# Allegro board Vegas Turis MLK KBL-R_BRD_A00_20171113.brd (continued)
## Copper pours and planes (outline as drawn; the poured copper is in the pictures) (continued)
+DC_IN on TOP: 80.87,167.46 80.07,168.25 78.24,168.25 77.99,168.51 77.22,168.51 76.67,169.06 68.06,169.06 66.11,171.01 66.11,174.44 66,174.55 65.23,174.55 64.6,175.19 64.6,176.63 64.62,176.66 64.62,178.08 67.52,180.98 70.14,180.98 70.72,180.39 70.72,178.21 71.01,177.92 71.6,177.92 71.83,177.69 71.83,176.59 72.06,176.37 75.91,176.37 76.44,175.84 76.44,173.17 76.69,172.93 80.72,172.93 81.25,172.4 83.19,172.4 83.65,171.93 84.73,171.93 85.51,171.15 85.51,168.31 85.45,168.25 84.74,168.25 83.95,167.46 ; 14 cut-outs
+DC_IN on BOTTOM: 74.88,165.81 74.46,166.22 74.46,172.07 69.91,176.63 68.23,176.63 68.14,176.72 68.14,177.26 68.14,177.26 68.14,180.55 68.33,180.74 70.35,180.74 70.67,180.42 70.67,179.5 76.94,173.22 78.47,173.22 78.77,172.92 78.77,170.55 76.86,168.64 76.86,166.11 76.56,165.81
+SDC_IN on TOP: 119.28,160.38 119.03,160.62 119.03,163.78 119.11,163.86 120.28,163.86 120.35,163.93 120.35,165.28 120.61,165.53 120.61,165.58 120.66,165.64 122.31,165.64 122.33,165.61 122.33,160.61 122.1,160.38
+UZ12_TPM on BOTTOM: 160.3,52.71 160.19,52.83 160.19,54.08 159.4,54.87 159.4,54.89 157.8,56.48 157.8,57.06 157.89,57.15 160.23,57.15 160.82,56.56 160.82,52.78 160.75,52.71 ; 4 cut-outs
+V_VREF_PATH2 on TOP: 96.13,17.05 96.08,17.1 96.08,17.61 96.19,17.73 96.79,17.73 96.8,17.73 97.33,17.73 97.92,18.33 98.33,18.33 98.41,18.24 98.41,17.8 97.66,17.05 ; 1 cut-out
+VCHGR on TOP: 140.77,160.53 140.55,160.76 140.55,167.63 140.98,168.06 144.51,168.06 144.96,167.62 144.96,161 144.48,160.53
+VCHGR on BOTTOM: 140.85,162.08 140.67,162.26 140.67,169.17 141.26,169.75 145.35,169.75 145.5,169.6 145.5,162.36 145.22,162.08
AD+ on TOP: 99.09,161.41 96.79,163.7 92.51,163.7 89.64,166.58 86.31,166.58 85.81,167.08 85.81,171.48 85.22,172.06 85.22,172.49 85.34,172.61 97.5,172.61 99.33,170.78 99.33,168.56 100.56,167.34 101.11,167.34 101.3,167.14 102.4,167.14 102.41,167.15 102.54,167.15 102.73,167.34 112.4,167.34 113.57,168.51 115.04,168.51 115.5,168.05 117.82,168.05 118.04,168.27 119.07,168.27 119.11,168.23 119.11,167.67 118.86,167.41 118.45,167.41 118.3,167.26 118.3,166.06 118.72,165.64 118.72,161.66 118.46,161.41 ; 5 cut-outs
AMBER_LED_BAT on BOTTOM: 186.95,11.75 186.73,11.97 186.73,12.73 187.25,13.25 188.5,13.25 188.5,13.25 189.96,13.25 190.15,13.06 190.15,12.47 189.92,12.24 189.87,12.24 189.37,11.75 ; 2 cut-outs
AUD_AGND on TOP: 164.57,12.39 164.33,12.63 164.33,15.74 164.34,15.75 164.34,17.21 164.44,17.31 165.5,17.31 166.3,16.5 166.3,14.77 166.18,14.65 166.18,12.74 165.83,12.39 ; 7 cut-outs
AUD_AGND on TOP: 173.31,11.59 173.25,11.65 173.25,12.57 174.18,13.5 174.18,13.7 174.38,13.89 177.61,13.89 178.02,14.3 181.39,14.3 181.64,14.05 181.64,13.36 181.44,13.16 178.12,13.16 176.54,11.59 ; 8 cut-outs
AUD_AGND on BOTTOM: 185.35,22.01 187.49,22.01 188.29,21.2 190.37,21.2 190.4,21.18 190.4,20.93 190.37,20.9 188.19,20.9 188.09,20.8 187.1,20.8 186.97,20.94 185.32,20.94 185.25,21.02 185.25,21.9
AUD_AGND on BOTTOM: 168.12,10.65 165.51,13.26 165.51,14.58 164.88,15.22 164.88,15.65 165.07,15.84 165.44,15.84 165.85,15.43 167.86,15.43 168.04,15.24 168.04,14.09 169.8,12.33 172.56,12.33 172.63,12.4 176.09,12.4 176.54,11.95 176.54,11.25 176.38,11.1 176.02,11.1 176,11.11 172.33,11.11 171.87,10.65 ; 1 cut-out
AUD_AGND on BOTTOM: 178.71,13.49 178.63,13.58 178.63,14.57 178.5,14.69 178.5,15.35 178.65,15.5 179.03,15.5 179.03,15.5 179.53,15.5 179.84,15.81 179.84,16.68 179.99,16.83 180.74,16.83 180.99,16.59 180.99,15.61 181.56,15.04 181.56,13.92 181.13,13.49 ; 3 cut-outs
AUD_AGND on L2: 176.56,11.59 170.45,11.59 170.28,11.76 170.28,12.42 170.28,12.43 170.28,14.3 170.79,14.81 171.54,14.81 172.01,15.28 172.01,15.62 171.83,15.8 168.83,15.8 167.77,14.75 166.42,14.75 166.23,14.55 166.23,12.79 165.86,12.42 164.72,12.42 164.47,12.67 164.47,15.87 165.31,16.7 167.27,16.7 167.33,16.64 174.33,16.64 174.44,16.75 174.44,21.14 175.72,22.43 184,22.43 184.17,22.27 187.3,22.27 188.55,21.03 190.15,21.03 190.39,20.79 190.39,20.78 190.42,20.75 190.42,16.26 190.1,15.94 188.1,15.94 187.72,15.56 185.96,15.56 185.79,15.72 184.73,15.72 184.42,15.41 184.42,14.35 183.22,13.15 178.11,13.15
AUD_AGND on L5GND: 168.15,10.62 166.47,12.3 165.14,12.3 164.86,12.58 164.86,15.68 165.08,15.9 165.37,15.9 165.55,16.07 165.55,16.86 166.02,17.33 166.93,17.33 167.3,17.7 168.84,17.7 169.04,17.89 170.19,17.89 170.28,17.81 170.28,16.92 169.73,16.37 168.95,16.37 168.2,15.62 168.2,13.72 169.77,12.15 171.91,12.15 172.25,12.49 172.25,14.82 172.01,15.07 172.01,16.6 172.06,16.65 174.18,16.65 174.43,16.9 174.43,20.64 175.96,22.17 187.36,22.17 188.32,21.22 190.37,21.22 190.4,21.19 190.4,15.88 190.39,15.88 188.1,15.88 187.57,15.35 186.13,15.35 185.83,15.65 184.69,15.65 184.43,15.38 184.43,14.37 183.2,13.14 180.02,13.14 179.79,13.38 178.87,13.38 178.25,12.75 178.25,12.29 177.95,11.99 177.32,11.99 176.42,11.08 172.33,11.08 171.87,10.62
AUD_SPK_L+ on TOP: 155,15.32 155,15.98 155.26,16.24 155.26,18.27 155.76,18.77 156.27,18.77 156.52,18.52 156.52,18.09 156.06,17.63 156.06,15.34 156.04,15.32
AUD_SPK_L+_C on TOP: 154.74,11.69 154.44,11.99 154.44,13.74 155,14.3 155,14.68 155.13,14.81 155.96,14.81 156.06,14.71 156.06,11.79 155.96,11.69
AUD_SPK_L+_C on BOTTOM: 154.41,11.36 154.39,11.38 154.39,13.79 154.54,13.95 155.02,13.95 155.18,13.79 155.18,13.29 155.02,13.13 155.02,11.43 154.95,11.36
AUD_SPK_L- on TOP: 153.3,15.27 153.19,15.37 153.19,16.05 153.27,16.13 153.3,16.13 153.65,16.49 153.65,17.73 153.66,17.74 153.66,18.56 154.57,19.46 154.95,19.46 155.35,19.05 155.35,18.85 154.38,17.88 154.38,16.43 154.24,16.28 154.24,15.34 154.19,15.34 154.11,15.27
AUD_SPK_L-_C on TOP: 153.35,11.71 153.22,11.84 153.22,14.68 153.3,14.76 154.26,14.76 154.39,14.63 154.39,13.97 154.21,13.79 154.21,11.89 154.03,11.71
AUD_SPK_L-_C on BOTTOM: 153.45,11.38 153.19,11.64 153.19,13.69 153.35,13.85 153.8,13.85 154.03,13.62 154.03,11.43 153.98,11.38
AUD_SPK_R+ on TOP: 158.88,15.22 158.78,15.32 158.78,16.95 159.16,17.33 160.1,17.33 160.35,17.57 160.66,17.57 161.11,17.11 161.11,16.87 160.56,16.32 159.83,16.32 159.8,16.28 159.8,15.29 159.72,15.22 ; 1 cut-out
AUD_SPK_R+_C on TOP: 158.96,11.66 158.68,11.94 158.68,13.69 158.69,13.71 158.69,14.65 158.83,14.78 159.7,14.78 159.75,14.73 159.75,11.79 159.62,11.66
AUD_SPK_R+_C on BOTTOM: 156.5,11.33 156.37,11.46 156.37,12.98 156.45,13.06 157.44,13.06 158.17,13.79 159.39,13.79 159.57,13.62 159.57,12.98 157.92,11.33
AUD_SPK_R- on TOP: 156.93,15.72 156.88,15.78 156.88,16.72 156.94,16.78 156.94,18.31 157.33,18.7 158.3,18.7 158.35,18.65 158.35,17.68 158.22,17.55 157.92,17.55 157.81,17.44 157.81,16.74 157.94,16.6 157.94,15.8 157.87,15.72 ; 2 cut-outs
AUD_SPK_R-_C on TOP: 156.57,11.66 156.45,11.79 156.45,15.12 156.6,15.27 157.84,15.27 158,15.12 158,11.79 157.87,11.66 ; 1 cut-out
AUD_SPK_R-_C on BOTTOM: 155.4,11.38 155.4,13.46 156.4,14.45 156.98,14.45 157.23,14.2 157.23,13.79 157,13.57 156.52,13.57 156.04,13.08 156.04,11.46 155.96,11.38
BT+ on TOP: 145,171.39 144.65,171.74 144.65,172.41 144.97,172.73 147.03,172.73 147.58,173.28 147.58,174.2 147.89,174.5 150.48,174.5 150.6,174.37 150.6,173.56 149.66,172.62 149.63,172.62 148.4,171.39
BT+ on TOP: 126.52,172.87 126.21,173.19 126.21,174.47 126.41,174.68 128.2,174.68 128.26,174.61 128.26,173.01 128.12,172.87
BT+ on TOP: 166.73,177.93 166.04,178.62 166.04,182.2 163.25,184.98 163.25,186.39 163.56,186.69 166.83,186.69 167.52,186.01 167.52,181.05 168.95,179.62 168.95,178.19 168.69,177.93
BT+ on BOTTOM: 141.59,170.41 141.51,170.49 141.51,173.28 142.04,173.81 143.62,173.81 143.64,173.84 145.08,173.84 147.64,176.4 147.64,177.14 147.82,177.32 150.25,177.32 150.25,177.32 150.55,177.62 150.55,178.34 152.71,180.49 155.02,180.49 155.51,180.99 162.71,180.99 163.22,181.49 163.22,186.73 163.43,186.95 166.96,186.95 167.37,186.54 167.37,178.44 166.4,177.47 158.38,177.47 157.74,176.84 154.36,176.84 154.35,176.82 153.08,176.82 152.66,176.41 152.66,175.29 151.82,174.45 151.82,173.08 151.46,172.71 150.93,172.71 150.93,172.71 150.54,172.71 148.24,170.41 ; 7 cut-outs
BT+ on L3: 167.96,184.39 168.86,183.49 168.86,176.48 167.43,175.05 157.78,175.05 156.06,173.33 155.89,173.33 155.13,172.57 147.89,172.57 147.4,173.05 147.4,174.81 148.32,175.72 148.32,177.88 149.59,179.15 149.59,180.37 149.94,180.72 155.49,180.72 155.79,181.03 155.79,184.39 156.35,184.94 162.62,184.94 163.15,185.47 163.15,186.56 163.45,186.86 167.77,186.86 167.96,186.66
DCBATOUT on TOP: 91.08,181.88 91.08,181.89 90.65,181.89 90.37,182.17 90.37,183.51 90.51,183.66 95.64,183.66 95.91,183.39 95.91,182.19 95.6,181.88 ; 1 cut-out
DCBATOUT on TOP: 150.4,115.05 148.98,116.47 148.98,118.57 149.27,118.87 151.49,118.87 152.23,119.61 153.55,119.61 154.31,120.37 158.1,120.37 158.31,120.16 159.58,120.16 159.8,120.37 163.82,120.37 163.95,120.25 163.95,115.72 163.74,115.52 162.45,115.52 161.76,116.21 158.19,116.21 157.39,115.42 151.05,115.42 150.68,115.05 ; 2 cut-outs
DCBATOUT on TOP: outline of 121 points within 31.08,13.41 144.75,164.95 ; 31 cut-outs
DCBATOUT on TOP: 189.36,173.92 188.98,174.3 188.98,174.86 189.62,175.49 191.24,175.49 191.5,175.24 191.5,174.26 191.16,173.92 ; 2 cut-outs
DCBATOUT on BOTTOM: 50.5,15.44 49.77,16.17 49.77,16.86 49.95,17.05 52.01,17.05 52.22,16.84 52.22,15.68 51.98,15.44
DCBATOUT on BOTTOM: outline of 215 points within 95.19,67.79 190.71,184.82 ; 12 cut-outs
DCBATOUT on BOTTOM: 189.42,173.23 189.34,173.31 189.34,175.19 189.74,175.59 191.28,175.59 191.49,175.38 191.49,174.41 191.69,174.21 191.69,173.25 191.66,173.23
DCBATOUT on L4: 141.28,157.2 141.56,156.92 145.6,156.92 145.76,157.08 145.76,169.27 147.25,170.77 150.61,170.77 153.17,173.33 157.63,173.33 158.13,173.83 191.29,173.83 191.86,174.41 191.86,175.59 189.45,178.01 183.39,178.01 183.07,178.33 152.86,178.33 150.55,176.02 148.5,176.02 142.2,169.72 142.2,160.33 141.28,159.42
DCBATOUT_LCD on TOP: 93.68,175.68 93.42,175.94 93.42,177.81 93.06,178.17 91.6,178.17 91.49,178.28 91.49,180.02 91.65,180.19 95.01,180.19 95.1,180.1 95.1,177.93 95.27,177.76 95.27,175.8 95.15,175.68 ; 4 cut-outs
DCBATOUT_LCD on BOTTOM: 94.48,176.03 94.45,176.06 94.45,177.81 94.55,177.91 95.07,177.91 95.32,177.66 95.32,176.05 95.29,176.03
EC_AGND on BOTTOM: 154.92,38.38 154.76,38.54 154.76,39.57 154.92,39.74 155.53,39.74 155.79,40.01 156.4,40.01 156.77,39.63 158.03,39.63 158.06,39.6 158.06,39.47 158.03,39.43 156.29,39.43 155.49,38.63 155.49,38.55 155.32,38.38 ; 1 cut-out
EC_AGND on BOTTOM: 151.21,33.59 150.03,34.77 150.03,35.29 149.6,35.72 149.6,36.79 149.89,37.08 149.89,37.4 150.31,37.82 152.14,37.82 152.35,37.61 152.35,35.56 152.27,35.48 151.84,35.48 151.32,36 150.91,36 150.74,35.83 150.74,34.9 151.36,34.28 152.13,34.28 152.31,34.11 152.31,33.63 152.27,33.59 ; 6 cut-outs
EMMC_RCOMP on TOP: 139.77,78.43 139.77,78.44 139.48,78.44 139.28,78.64 139.28,79.75 139.39,79.86 140,79.86 140.45,79.42 141.31,79.42 141.58,79.15 141.58,78.7 141.31,78.43 ; 1 cut-out
EMMC_VCC on TOP: 175.01,55.45 175,55.46 174.49,55.46 173.82,56.14 173.82,59.21 172.83,60.2 172.83,62.8 174.22,64.19 176.66,64.19 177.89,62.96 177.89,56.67 176.66,55.45 ; 6 cut-outs
EMMC_VCCQ on BOTTOM: 175.11,51.61 174.76,51.97 174.23,51.97 173.64,52.55 173.64,52.78 172.93,53.5 172.93,58.24 173.1,58.42 174.03,58.42 174.29,58.15 174.29,53.24 174.78,52.75 177.33,52.75 177.45,52.63 177.45,52.12 177.25,51.92 176.97,51.92 176.66,51.61 ; 2 cut-outs
EMMC_VCCQ on BOTTOM: 177.33,62.06 176.97,62.43 176.97,64.69 176.56,65.09 176.56,66.11 177.34,66.89 179.99,66.89 180.67,67.58 183.72,67.58 184.87,66.42 184.87,64.75 184,63.88 182.64,63.88 180.82,62.06 ; 4 cut-outs
EMMC_VCCQ on L3: 180.48,60.19 177.46,57.17 173.14,57.17 172.81,57.51 172.81,58.87 173.28,59.34 176.37,59.34 178.2,61.17 178.2,63.8 178.76,64.35 180.32,64.35 180.48,64.2
FAN_TACH1_C on TOP: 109.4,138.11 109.21,138.31 109.21,138.89 108.9,139.2 108.9,139.49 108.89,139.49 108.89,140.3 109.08,140.49 109.71,140.49 109.93,140.26 110.42,140.26 110.5,140.18 110.5,138.4 110.22,138.11 ; 1 cut-out
FAN_TACH1_C on BOTTOM: 109.2,138.66 109.07,138.79 109.07,139.62 109.23,139.78 112.08,139.78 112.2,139.66 112.2,139.02 112.09,138.9 110.18,138.9 109.94,138.66
FAN_VCC1 on TOP: 94.57,138.83 94.52,138.88 94.52,141.61 95.63,142.72 99.56,142.72 100.24,142.05 100.24,141.04 100.08,140.89 99.59,140.89 98.93,141.55 97.08,141.55 96.48,140.94 95.44,140.94 95.29,140.79 95.29,138.9 95.22,138.83 ; 2 cut-outs
FAN_VCC1 on TOP: 111.11,134.56 110.88,134.79 110.88,135.73 110.58,136.03 107.87,136.03 107.74,136.16 107.74,137.37 107.95,137.58 107.95,137.58 108.23,137.85 110.88,137.85 111.58,137.15 111.58,136.21 112.09,135.7 112.09,134.8 111.85,134.56 ; 4 cut-outs
FAN_VCC1 on BOTTOM: 109.71,137.16 109.38,137.49 109.38,138.32 109.57,138.51 110.32,138.51 110.34,138.53 112.2,138.53 112.26,138.47 112.26,137.75 111.68,137.16
FP_PWR on BOTTOM: 189.33,54.81 189.07,55.07 189.07,56.86 189.54,57.33 189.91,57.33 190.2,57.04 190.2,56.64 190.35,56.49 191.08,56.49 191.14,56.55 191.96,56.55 192.15,56.36 192.15,54.98 192.05,54.88 190.31,54.88 190.25,54.81 ; 4 cut-outs
GT_CORE on TOP: 113.95,90.02 113.77,90.2 111.51,90.2 111.41,90.3 111.41,91.67 111.46,91.72 111.82,91.72 112.05,91.95 112.05,92.25 112.21,92.41 113.11,92.41 113.39,92.69 113.7,92.69 113.97,92.41 114.97,92.41 115.33,92.05 115.33,90.33 115.02,90.02
GT_CORE on BOTTOM: 112.1,91.37 111.96,91.51 111.96,92.14 111.6,92.5 110.36,92.5 110.01,92.84 110.01,93.25 110.12,93.35 114.84,93.35 114.94,93.25 114.94,92.74 115.2,92.48 115.2,91.57 114.99,91.37
GTX_CORE on TOP: 112.05,81.87 112.04,81.87 111.58,81.87 111.49,81.97 111.49,82.95 111.49,82.95 111.36,83.09 111.36,83.57 111.51,83.72 114.4,83.72 114.66,83.97 114.66,84.63 114.69,84.66 115.65,84.66 115.9,84.42 115.9,82.31 115.77,82.18 115.56,82.18 115.24,81.87
GTX_CORE on BOTTOM: 110.55,81.13 110.42,81.26 110.42,81.46 110.62,81.66 111.23,81.66 111.34,81.76 111.34,82.58 111.45,82.69 111.41,82.73 111.41,83.57 111.54,83.7 115.98,83.7 116.11,83.57 116.11,82.58 116.25,82.44 116.25,81.9 115.93,81.59 115.37,81.59 115.25,81.71 115.07,81.54 112.88,81.54 112.53,81.18 112.35,81.18 112.17,81.36 111.79,81.36 111.64,81.21 111.44,81.21 111.31,81.33 110.98,81.33 110.78,81.13
HDMI_PLL_GND on TOP: 17,48.8 16.87,48.92 16.87,49.61 16.92,49.66 20.35,49.66 20.63,49.38 23.81,49.38 25.2,50.78 25.2,53.49 25.31,53.6 26.58,53.6 26.76,53.42 26.76,50.17 25.38,48.8 ; 1 cut-out
HDMI_PLL_GND on BOTTOM: 16.37,45.34 16.3,45.41 16.3,52.66 16.52,52.88 17.51,52.88 17.79,52.6 17.79,50.54 17.55,50.3 17.55,45.59 17.3,45.34
JGND on TOP: 76.93,173.08 76.75,173.26 76.75,175.92 75.9,176.77 75.9,180.51 76.16,180.77 80.08,180.77 81.11,179.73 81.11,173.49 80.7,173.08 ; 2 cut-outs
JGND on BOTTOM: 76.19,176.55 76.11,176.64 76.11,180.5 76.37,180.76 78.73,180.76 79.07,180.42 79.07,176.77 78.86,176.55
LCDVDD on TOP: 97.53,176.13 96.98,176.68 95.61,176.68 95.55,176.75 95.55,178.74 95.88,179.07 97.39,179.07 98.43,178.03 98.43,178.02 98.43,177.46 98.35,177.38 98.35,176.28 98.2,176.13 ; 1 cut-out
LCDVDD_LCD on TOP: 95.42,173.26 94.97,173.7 94.97,174.73 94.98,174.74 94.98,174.99 95.48,175.49 95.48,176.03 95.72,176.27 97.19,176.27 97.49,175.96 97.99,175.96 98.1,175.85 98.1,175.39 98.36,175.12 98.36,174.17 97.45,173.26 ; 2 cut-outs
LCDVDD_LCD on BOTTOM: 96.07,173.87 95.34,174.6 95.34,175.37 95.87,175.9 95.87,176.92 95.9,176.95 97.91,176.95 97.92,176.94 97.92,175.89 98.46,175.36 98.46,174.59 97.74,173.87
LOM_TCT on TOP: 28.14,172.98 27.97,173.14 27.97,177.79 28.25,178.07 30.09,178.07 30.35,177.81 30.35,175.73 30.53,175.54 31.17,175.54 31.34,175.37 31.34,174.17 30.14,172.98 ; 2 cut-outs
LOM_TCT on BOTTOM: 28.14,172.98 27.97,173.14 27.97,177.79 28.25,178.07 31.05,178.07 31.31,177.81 31.31,174.15 30.13,172.98
M_VREF_CA_DIMMA on TOP: 112.04,17.12 111.73,17.43 111.73,19.29 111.83,19.39 113.11,19.39 113.29,19.21 113.29,17.3 113.11,17.12 ; 1 cut-out
M_VREF_CA_DIMMB on TOP: 97.28,18.94 97.23,18.99 97.23,20.29 97.28,20.35 99.79,20.35 100.66,21.22 100.87,21.22 101.12,20.98 101.12,19.93 100.58,19.4 98.69,19.4 98.23,18.94 ; 4 cut-outs
MCT on BOTTOM: 17.62,182.39 17.46,182.55 14.99,182.55 14.89,182.66 14.89,183.34 15.44,183.89 15.44,185.78 15.57,185.92 16.8,185.92 16.88,185.84 16.88,185.15 16.88,185.15 16.88,184.1 18.31,182.67 18.31,182.52 18.17,182.39
Net_49 on L5GND: 22.57,175.04 23.33,175.04
Net_50 on L5GND: 22.57,171.99 23.33,171.99
Net_51 on L5GND: 24.1,178.09 24.86,178.09
Net_52 on L5GND: 24.1,176.56 24.86,176.56
Net_53 on L5GND: 24.1,171.99 24.86,171.99
Net_54 on L5GND: 24.1,175.04 24.86,175.04
Net_55 on L5GND: 24.1,173.52 24.86,173.52
Net_56 on L5GND: 21.05,170.47 21.81,170.47
Net_57 on L5GND: 24.1,170.47 24.86,170.47
Net_58 on L5GND: 22.57,170.47 23.33,170.47
Net_59 on L5GND: 19.52,170.47 20.29,170.47
Net_60 on L5GND: 18,178.09 18.76,178.09
Net_61 on L5GND: 16.48,178.09 17.24,178.09
Net_62 on L5GND: 16.48,170.47 17.24,170.47
Net_63 on L5GND: 16.48,171.99 17.24,171.99
Net_64 on L5GND: 14.95,170.47 15.71,170.47
Net_65 on L5GND: 14.95,171.99 15.71,171.99
Net_66 on L5GND: 14.95,173.52 15.71,173.52
Net_67 on L5GND: 18,173.52 18.76,173.52
Net_68 on L5GND: 16.48,173.52 17.24,173.52
Net_69 on L5GND: 18,175.04 18.76,175.04
Net_70 on L5GND: 16.48,175.04 17.24,175.04
Net_71 on L5GND: 16.48,176.56 17.24,176.56
Net_72 on L5GND: 18,170.47 18.76,170.47
Net_73 on L5GND: 18,171.99 18.76,171.99
Net_74 on L5GND: 21.05,181.14 21.81,181.14
Net_75 on L5GND: 21.05,179.61 21.81,179.61
Net_76 on L5GND: 24.1,179.61 24.86,179.61
Net_77 on L5GND: 22.57,179.61 23.33,179.61
Net_78 on L5GND: 19.52,181.14 20.29,181.14
Net_79 on L5GND: 19.52,179.61 20.29,179.61
Net_80 on L5GND: 17.95,184.95 18.71,184.95
Net_81 on L5GND: 16.43,184.95 17.19,184.95
Net_82 on L5GND: 14.9,184.95 15.66,184.95
Net_83 on L5GND: 17.95,183.42 18.71,183.42
Net_84 on L5GND: 16.43,183.42 17.19,183.42
Net_85 on L5GND: 14.9,183.42 15.66,183.42
Net_102 on L2: 18.81,169.99 19.57,169.99
Net_102 on L2: 23.38,171.52 24.14,171.52
Net_102 on L2: 24.9,173.04 25.66,173.04
Net_102 on L2: 24.9,176.09 25.66,176.09
Net_102 on L2: 23.38,169.99 24.14,169.99
Net_102 on L2: 23.38,173.04 24.14,173.04
Net_102 on L2: 21.85,171.52 22.62,171.52
Net_102 on L2: 23.38,174.56 24.14,174.56
Net_102 on L2: 18.81,171.52 19.57,171.52
Net_102 on L2: 24.9,174.56 25.66,174.56
Net_102 on L2: 21.85,169.99 22.62,169.99
Net_102 on L2: 24.9,171.52 25.66,171.52
Net_102 on L2: 24.9,169.99 25.66,169.99
Net_103 on L2: 17.28,169.99 18.04,169.99
Net_103 on L2: 17.28,171.52 18.04,171.52
Net_104 on L2: 15.76,171.52 16.52,171.52
Net_104 on L2: 15.76,169.99 16.52,169.99
Net_105 on L2: 14.23,169.99 15,169.99
Net_105 on L2: 14.23,171.52 15,171.52
Net_106 on L2: 17.28,173.04 18.04,173.04
Net_107 on L2: 15.76,173.04 16.52,173.04
Net_108 on L2: 17.28,174.56 18.04,174.56
Net_109 on L2: 15.76,174.56 16.52,174.56
Net_110 on L2: 17.28,176.09 18.04,176.09
Net_111 on L2: 15.76,176.09 16.52,176.09
Net_112 on L2: 15.76,177.61 16.52,177.61
Net_113 on L2: 17.28,177.61 18.04,177.61
Net_114 on L2: 18.81,179.14 19.57,179.14
Net_115 on L2: 24.9,177.61 25.66,177.61
Net_116 on L2: 24.9,179.14 25.66,179.14
Net_117 on L2: 23.38,179.14 24.14,179.14
Net_118 on L2: 20.33,179.14 21.09,179.14
Net_119 on L2: 20.33,180.66 21.09,180.66
Net_120 on L2: 18.55,183.45 19.31,183.45
Net_121 on L2: 17.03,183.45 17.79,183.45
Net_122 on L2: 15.5,183.45 16.27,183.45
Net_123 on L2: 13.98,183.45 14.74,183.45
Net_124 on L2: 18.55,184.98 19.31,184.98
Net_124 on L3: 25.58,177.57 26.34,177.57
Net_124 on L3: 27.1,179.09 27.86,179.09
Net_124 on L3: 22.53,171.47 23.29,171.47
Net_124 on L3: 16.43,176.04 17.19,176.04
Net_124 on L3: 27.1,176.04 27.86,176.04
Net_124 on L3: 16.94,185.19 17.7,185.19
Net_124 on L3: 27.1,174.52 27.86,174.52
Net_124 on L3: 17.96,173 18.72,173
Net_124 on L3: 27.1,171.47 27.86,171.47
Net_124 on L3: 27.1,173 27.86,173
Net_124 on L3: 16.43,171.47 17.19,171.47
Net_124 on L3: 16.94,183.66 17.7,183.66
Net_124 on L3: 16.43,177.57 17.19,177.57
Net_124 on L3: 18.46,183.66 19.23,183.66
Net_124 on L3: 27.1,177.57 27.86,177.57
Net_124 on L4: 18.42,184.5 19.19,184.5
Net_124 on L4: 18.4,171.48 19.17,171.48
Net_125 on L2: 17.03,184.98 17.79,184.98
Net_125 on L3: 25.58,176.04 26.34,176.04
Net_125 on L3: 15.42,185.19 16.18,185.19
Net_125 on L3: 19.48,171.47 20.24,171.47
Net_125 on L3: 25.58,173 26.34,173
Net_125 on L3: 25.58,171.47 26.34,171.47
Net_125 on L3: 15.42,183.66 16.18,183.66
Net_125 on L3: 25.58,174.52 26.34,174.52
Net_125 on L3: 14.91,171.47 15.67,171.47
Net_125 on L3: 17.96,174.52 18.72,174.52
Net_125 on L3: 25.58,179.09 26.34,179.09
Net_125 on L3: 16.43,173 17.19,173
Net_125 on L4: 18.4,173.01 19.17,173.01
Net_125 on L4: 26.02,174.53 26.79,174.53
Net_125 on L4: 16.9,184.5 17.66,184.5
Net_125 on L4: 26.02,171.48 26.79,171.48
Net_125 on L4: 26.02,173.01 26.79,173.01
Net_125 on L4: 16.88,171.48 17.64,171.48
Net_126 on L2: 15.5,184.98 16.27,184.98
Net_126 on L3: 13.38,171.47 14.15,171.47
Net_126 on L3: 24.05,173 24.81,173
Net_126 on L3: 24.05,171.47 24.81,171.47
Net_126 on L3: 24.05,174.52 24.81,174.52
Net_126 on L3: 14.91,173 15.67,173
Net_126 on L3: 24.05,179.09 24.81,179.09
Net_126 on L3: 13.89,185.19 14.65,185.19
Net_126 on L3: 24.05,176.04 24.81,176.04
Net_126 on L3: 16.43,174.52 17.19,174.52
Net_126 on L3: 13.89,183.66 14.65,183.66
Net_126 on L3: 17.96,171.47 18.72,171.47
Net_126 on L4: 26.02,179.1 26.79,179.1
Net_126 on L4: 26.02,176.05 26.79,176.05
Net_126 on L4: 24.5,171.48 25.26,171.48
Net_126 on L4: 16.88,176.05 17.64,176.05
Net_126 on L4: 15.38,184.5 16.14,184.5
Net_126 on L4: 16.88,174.53 17.64,174.53
Net_126 on L4: 16.88,177.58 17.64,177.58
Net_126 on L4: 24.5,174.53 25.26,174.53
Net_126 on L4: 24.5,173.01 25.26,173.01
Net_126 on L4: 26.02,177.58 26.79,177.58
Net_126 on L4: 16.88,173.01 17.64,173.01
Net_126 on L4: 15.36,171.48 16.12,171.48
Net_127 on L2: 13.98,184.98 14.74,184.98
Net_127 on L4: 15.36,174.53 16.12,174.53
Net_127 on L4: 13.85,184.5 14.61,184.5
Net_127 on L4: 15.36,173.01 16.12,173.01
Net_127 on L4: 24.5,179.1 25.26,179.1
Net_127 on L4: 22.98,173.01 23.74,173.01
Net_127 on L4: 15.36,176.05 16.12,176.05
Net_127 on L4: 22.98,171.48 23.74,171.48
Net_127 on L4: 22.98,174.53 23.74,174.53
Net_127 on L4: 15.36,177.58 16.12,177.58
Net_127 on L4: 24.5,176.05 25.26,176.05
Net_127 on L4: 13.83,171.48 14.59,171.48
Net_127 on L4: 24.5,177.58 25.26,177.58
ODD_PWR_5V on TOP: 182.01,84.39 181.82,84.58 181.82,84.91 182.02,85.12 183.5,85.12 183.8,85.42 183.8,87.14 183.88,87.21 187.19,87.21 187.53,86.88 187.53,84.81 187.12,84.39
ODD_PWR_5V on BOTTOM: 186.29,84.25 184.02,86.53 184.02,89.55 184.06,89.59 185.53,89.59 187.56,87.56 187.56,84.66 187.15,84.25 ; 4 cut-outs
PS_ID_R2 on TOP: 62.62,172.01 62.52,172.11 62.52,173.56 63.2,174.25 63.2,176.43 63.28,176.51 64.32,176.51 64.47,176.35 64.47,175.03 65.39,174.12 65.39,172.11 65.29,172.01
PU8201_36 on BOTTOM: 161.01,104.98 160.89,105.1 160.89,106 160.89,107.09 160.91,107.11 161.85,107.11 161.91,107.05 161.91,105.12 161.77,104.98
PU8201_39 on BOTTOM: 160.18,105.1 160.09,105.18 160.09,107.08 160.14,107.13 160.67,107.13 160.71,107.09 160.71,105.21 160.6,105.1
PWR_0D95V on BOTTOM: 147.12,147.5 146.9,147.73 146.9,149.79 146.88,149.8 146.88,149.93 146.29,150.52 145.96,150.52 145.81,150.67 145.81,154.04 145.87,154.1 147.38,154.1 148.85,152.63 148.85,148.03 148.32,147.5 ; 2 cut-outs
PWR_0D95V_PHASE on BOTTOM: 143.48,150.63 143.29,150.82 143.29,151.6 142.7,152.19 141.97,152.19 141.95,152.21 141.95,152.45 142.01,152.52 142.68,152.52 142.74,152.57 142.74,153.64 143.11,154.01 145.12,154.01 145.25,153.88 145.25,150.76 145.12,150.63
PWR_0D95V_PVDD on BOTTOM: 135.67,150.75 135.35,151.08 135.35,152.55 135.42,152.63 139.58,152.63 139.69,152.51 140.47,152.51 140.49,152.49 140.49,152.21 140.48,152.2 139.76,152.2 139.66,152.09 139.66,151.9 138.51,150.75 ; 8 cut-outs
PWR_1D0V on TOP: 168.69,71.25 168.13,71.81 168.13,76.33 168.14,76.34 168.14,77.31 168.28,77.45 172.85,77.45 173.18,77.12 173.18,74.58 174.86,72.9 174.86,71.55 174.56,71.25 ; 14 cut-outs
PWR_1D0V on BOTTOM: 169.07,72.49 168.18,73.38 168.18,77.17 168.35,77.33 172.92,77.33 173.31,76.94 173.31,73.1 172.7,72.49
PWR_1D0V_PH on BOTTOM: 180.14,72.6 179.99,72.75 179.99,73.31 180.09,73.41 180.09,75.54 180.07,75.57 178.9,75.57 178.54,75.21 178.54,74.6 177.53,73.59 174.96,73.59 174.43,74.12 174.43,77.5 174.94,78.01 179.53,78.01 180.3,77.24 180.3,76.56 180.45,76.41 180.83,76.41 180.98,76.25 180.98,72.8 180.78,72.6 ; 2 cut-outs
PWR_1D2V on TOP: 52.08,31.98 51.26,32.8 51.26,38.09 52.23,39.07 58.2,39.07 58.3,38.97 58.3,33.25 58.9,32.65 58.9,32.04 58.83,31.98 ; 6 cut-outs
PWR_1D2V on BOTTOM: 47.14,32.82 47.03,32.93 47.03,38.67 47.71,39.34 57.75,39.34 57.92,39.17 57.92,33.78 57.42,33.28 52.71,33.28 52.69,33.26 52.24,33.26 51.8,32.82 ; 4 cut-outs
PWR_1D35V_PG on BOTTOM: 194.47,167.72 194.39,167.79 194.39,169.04 194.98,169.62 194.98,171.15 194.67,171.45 194.67,171.93 194.95,172.21 196.3,172.21 196.4,172.11 196.4,171.73 195.82,171.15 195.82,169.6 195.23,169.01 195.23,168.2 194.75,167.72 ; 1 cut-out
PWR_1D35V_PH on BOTTOM: 193.71,159.6 192.44,160.87 192.44,165.18 193.38,166.12 193.73,166.12 193.76,166.09 193.76,163.53 194.39,162.89 196.73,162.89 196.74,162.89 196.74,159.98 196.35,159.6 ; 2 cut-outs
PWR_1D35V_PH on L4: 194.6,162.89 193.67,163.82 193.67,164.71 193.48,164.9 192.49,164.9 192.44,164.85 192.44,160.89 193.73,159.59 196.35,159.59 196.73,159.97 196.73,162.61 196.45,162.89
PWR_1D35V_VCC on BOTTOM: 194.93,163.35 194.8,163.48 194.8,163.65 194.37,164.09 194.37,164.34 194.44,164.42 194.39,164.47 194.39,166.09 194.44,166.14 194.75,166.14 195.28,165.61 195.28,164.7 195.51,164.47 196.98,164.47 197.19,164.26 197.19,163.48 197.06,163.35
PWR_3D3V_DRVH2 on TOP: 40.59,61.03 40.46,61.16 40.46,62.94 40.59,63.06 41.1,63.06 41.22,62.94 41.22,61.16 41.1,61.03
PWR_3D3V_DRVL2 on TOP: 42.18,65.07 42.06,65.19 42.06,66.21 42.13,66.28 43.48,66.28 43.51,66.25 43.51,65.08 43.5,65.07
PWR_3D3V_LL2 on TOP: 38.54,59.39 38.3,59.62 38.3,62.94 38.43,63.06 40.21,63.06 40.21,60.9 40.33,60.78 41.48,60.78 42.06,61.36 42.06,64.51 42.24,64.69 46.33,64.69 46.43,64.59 46.43,59.89 45.93,59.39
PWR_3D3V_LL2 on BOTTOM: 38.48,59.86 38.3,60.04 38.3,64.46 38.68,64.84 45.41,64.84 45.47,64.9 45.47,66.4 45.49,66.42 46.43,66.42 46.44,66.41 46.44,60.24 46.06,59.86
PWR_5V_DRVH1 on TOP: 57.96,61.04 57.84,61.17 57.84,62.94 57.96,63.07 58.6,63.07 58.72,62.94 58.72,61.29 58.47,61.04
PWR_5V_DRVL1 on TOP: 50.41,71.99 49.4,73 49.4,73.89 49.42,73.92 50.32,73.92 51.01,73.23 51.01,72.24 50.75,71.99
PWR_5V_DRVL1 on TOP: 50.49,65.09 50.37,65.22 50.37,66.11 50.49,66.24 51.76,66.24 51.76,65.22 51.64,65.09
PWR_5V_LL1 on TOP: 50.94,60.01 50.62,60.33 50.62,64.59 50.75,64.71 54.81,64.71 54.94,64.59 54.94,63.32 55.19,63.06 57.48,63.06 57.61,62.94 57.61,60.14 57.48,60.01
PWR_5V_LL1 on BOTTOM: 51.49,59.99 50.88,60.6 50.88,64.21 51.26,64.59 57.89,64.59 57.98,64.5 57.98,63.5 57.48,63 57.48,60.27 57.2,59.99
PWR_CHG_BATDRV on BOTTOM: 130.96,174.46 130.86,174.56 130.86,175.08 131.24,175.46 132.11,175.46 132.14,175.43 132.14,175 131.6,174.46
PWR_CHG_HIDRV on TOP: 129.29,161.55 128.97,161.87 128.97,163.45 129.38,163.86 130.38,163.86 130.69,163.55 130.69,161.62 130.61,161.55
PWR_CHG_HIDRV on BOTTOM: 131.09,172.86 130.92,173.03 130.92,173.58 131.43,174.08 132.61,174.08 132.66,174.14 132.66,175.14 132.69,175.18 132.88,175.18 132.88,175.17 132.88,174.02 132.65,173.79 132.42,173.79 131.49,172.86
PWR_CHG_LODRV on BOTTOM: 134.15,166.7 134.06,166.79 134.06,168.03 133.69,168.41 133.69,169.22 133.79,169.32 134.68,169.32 134.83,169.17 134.83,166.78 134.75,166.7
PWR_CHG_LODRV on BOTTOM: 133.54,172.57 133.39,172.73 133.39,173.68 133.46,173.76 133.46,175.15 133.48,175.17 133.66,175.17 133.68,175.16 133.68,173.79 134.23,173.24 134.23,172.87 133.94,172.57
PWR_CHG_PHASE on TOP: 136.51,161.09 136.08,161.52 131.33,161.52 131.17,161.67 131.17,166.22 131.38,166.42 135.03,166.42 135.24,166.63 138.41,166.63 138.74,166.3 138.74,161.77 138.06,161.09
PWR_CHG_PHASE on BOTTOM: 132.03,171.83 131.97,171.89 131.97,172.59 131.98,172.6 131.98,173.12 132.46,173.61 132.68,173.61 133.06,173.98 133.06,175.12 133.1,175.17 133.27,175.17 133.28,175.15 133.28,173.75 133.11,173.58 133.11,171.98 132.96,171.83
PWR_CHG_PHASE on BOTTOM: 130.27,161.08 129.88,161.46 129.88,166.27 130.03,166.42 135.03,166.42 135.24,166.63 138.77,166.63 139.2,166.19 139.2,161.44 138.84,161.08 138.11,161.08 138.11,161.08
PWR_DCBATOUT_1D0V on TOP: 181.29,69.09 180.91,69.47 180.91,72.44 181.11,72.65 182.07,72.65 182.28,72.44 182.28,69.55 181.82,69.09
PWR_DCBATOUT_1D0V on BOTTOM: 181.59,67.97 181.31,68.25 181.31,71.38 180.96,71.73 180.96,72.34 181.31,72.7 181.31,76.25 181.46,76.41 182.61,76.41 182.76,76.25 182.76,73.38 182.87,73.27 183.43,73.27 184.01,72.69 184.2,72.69 184.73,72.15 184.73,68.67 184.03,67.97 ; 4 cut-outs
PWR_DCBATOUT_1D35V on BOTTOM: 190.99,166.37 189.54,167.82 189.54,172.87 189.69,173.03 191.32,173.03 191.5,172.85 191.5,172.82 192.72,172.82 192.84,172.7 192.84,172.7 192.92,172.62 192.92,170.33 192.87,170.28 192.03,170.28 191.75,170 191.75,169.14 193.28,167.62 193.28,166.42 193.23,166.37 ; 1 cut-out
PWR_DCBATOUT_3D3V on TOP: 37.21,63.42 36.98,63.65 36.98,71.5 37.14,71.66 41.65,71.66 41.73,71.58 41.73,63.68 41.47,63.42 ; 2 cut-outs
PWR_DCBATOUT_5V on TOP: 55.45,63.32 55.19,63.57 55.19,66.75 54.94,67 54.94,71.57 55.15,71.78 60.8,71.78 60.91,71.68 60.91,64.53 59.69,63.32 ; 2 cut-outs
PWR_DCBATOUT_VCCGTA on TOP: 116.66,126.09 116.37,126.38 116.37,128.46 117,129.1 119.67,129.1 120.21,128.55 120.21,126.34 119.96,126.09
PWR_DCBATOUT_VCCGTA on BOTTOM: 116.73,126.05 116.32,126.46 116.32,127.36 116.67,127.71 116.93,127.71 117.45,128.23 117.45,129.09 117.54,129.17 122,129.17 122.1,129.07 122.1,128.59 122.12,128.57 122.12,128.17 122.68,127.61 123.07,127.61 123.25,127.44 123.25,126.88 123.15,126.78 120.45,126.78 119.72,126.05
PWR_DCBATOUT_VCCGTB on TOP: 107.47,126.29 107.17,126.59 107.17,128.81 107.66,129.3 110.83,129.3 111.02,129.12 111.02,126.54 110.77,126.29
PWR_DCBATOUT_VCCGTB on BOTTOM: 107.53,126.26 107.13,126.66 107.13,127.37 108.52,128.75 108.52,129.21 108.62,129.31 112.84,129.31 113.01,129.14 113.01,128.68 114.05,127.64 114.05,127.08 113.85,126.88 111.36,126.88 110.74,126.26
PWR_DCBATOUT_VCCSA on TOP: 133.23,122.79 132.86,123.16 132.86,127.62 133.16,127.93 134.78,127.93 134.92,127.79 134.92,122.89 134.82,122.79 ; 1 cut-out
PWR_DCBATOUT_VCCSA on BOTTOM: 131.72,127.38 134.45,127.38 135.31,126.53 135.31,123.6 135.17,123.47 131.7,123.47 131.58,123.58 131.58,127.24
PWR_DCBATOUT_VCORE on TOP: 97.81,129.26 98.04,129.5 103.13,129.5 103.29,129.34 103.29,127.45 102.82,126.98 102.04,126.98 101.42,126.36 97.96,126.36 97.81,126.51
PWR_DCBATOUT_VCORE on BOTTOM: 98.21,126.36 97.81,126.76 97.81,129.17 98.17,129.53 103.54,129.53 103.68,129.39 103.68,128.79 104.73,127.74 104.73,127.18 104.53,126.98 102.04,126.98 101.42,126.36
PWR_DCBATOUT_VDDQ on BOTTOM: 48.74,17.12 48.51,17.35 48.51,24.49 48.81,24.79 52.45,24.79 52.68,24.56 52.68,17.76 52.22,17.29 49.75,17.29 49.57,17.12 ; 2 cut-outs
PWR_DCBATOUT_VGA_CORE1 on TOP: 165.19,114.06 164.1,115.16 164.1,119.1 164.09,119.11 164.09,120.32 164.12,120.35 164.9,120.35 165.12,120.13 165.12,119.51 165.48,119.15 172.28,119.15 172.75,118.69 172.75,116.5 173,116.25 174.25,116.25 174.33,116.18 174.33,115.41 174.25,115.34 168.75,115.34 168.53,115.11 168.53,114.12 168.47,114.06 ; 1 cut-out
PWR_DCBATOUT_VGA_CORE1 on BOTTOM: 166.05,114.41 165.93,114.52 165.93,117.29 166.92,118.27 166.92,119.78 166.93,119.79 167.92,119.79 168,119.71 168,118.25 168.08,118.18 173.79,118.18 174.06,117.91 174.06,116.54 174.37,116.24 174.37,115.45 174.27,115.36 168.39,115.36 168.39,115.35 167.87,114.82 167.87,114.6 167.67,114.41 ; 1 cut-out
PWR_DCBATOUT_VGA_CORE2 on TOP: 165.91,97.06 164.26,98.71 164.26,101.09 164.49,101.32 168.67,101.32 168.73,101.27 168.73,99.99 168.95,99.78 174.31,99.78 174.37,99.72 174.37,99.04 174.02,98.69 174.02,97.36 173.72,97.06 ; 1 cut-out
PWR_DCBATOUT_VGA_CORE2 on BOTTOM: 164.48,95.99 163.84,96.64 163.84,101.03 164.13,101.32 167.97,101.32 168.08,101.21 168.08,100.13 168.43,99.78 174.37,99.78 174.4,99.74 174.4,98.99 174.38,98.97 172.94,98.97 172.78,98.81 172.78,97.72 173.44,97.06 173.44,96.2 173.23,95.99
PWR_VCCGT_BOOTA on BOTTOM: 123.83,126.79 123.81,126.81 123.81,127.43 123.81,127.43 123.81,127.77 123.73,127.86 123.73,128.57 123.55,128.74 123.55,129.6 123.59,129.64 124.62,129.64 124.81,129.45 124.81,128.06 124.54,127.78 124.22,127.78 124.04,127.6 124.04,126.82 124,126.79 ; 1 cut-out
PWR_VCCGT_BOOTB on BOTTOM: 114.64,126.92 114.62,126.94 114.62,127.64 114.56,127.7 114.56,129.54 114.7,129.68 115.54,129.68 115.6,129.62 115.6,128.44 114.85,127.69 114.85,126.96 114.81,126.92
PWR_VCCGT_BOOTRA on BOTTOM: 123.43,126.79 123.41,126.81 123.41,127.5 123.41,127.55 123.22,127.74 122.73,127.74 122.24,128.23 122.24,129.59 122.31,129.65 123.22,129.65 123.36,129.51 123.36,128.62 123.59,128.4 123.59,128.39 123.59,127.8 123.62,127.77 123.62,126.81 123.6,126.79
PWR_VCCGT_BOOTRB on BOTTOM: 114.28,126.95 114.23,127 114.23,127.68 114.14,127.76 114.11,127.76 113.2,128.67 113.2,129.62 113.27,129.7 114.26,129.7 114.38,129.57 114.38,128.74 114.46,128.66 114.46,127.76 114.42,127.72 114.42,127 114.37,126.95
PWR_VCCGT_PWMA_RA on BOTTOM: 124.24,126.77 124.21,126.8 124.21,127.55 124.29,127.63 124.55,127.63 124.96,128.04 124.96,129.17 125.07,129.28 126.3,129.28 126.48,129.09 126.48,128.66 124.59,126.77 ; 1 cut-out
PWR_VCCGT_PWMB_RA on BOTTOM: 115.1,126.92 115.03,126.98 115.03,127.63 115.74,128.34 115.74,129.21 115.83,129.3 117.14,129.3 117.27,129.17 117.27,128.37 116.78,127.89 116.3,127.89 115.34,126.92 ; 2 cut-outs
PWR_VCCGT_SNB1 on BOTTOM: 117.51,121.46 117.46,121.52 117.46,122.89 117.91,123.34 118.37,123.34 118.65,123.62 119.23,123.62 119.36,123.5 119.36,121.52 119.31,121.46 ; 1 cut-out
PWR_VCCGT_SWA on BOTTOM: 120.91,119.31 120.37,119.84 120.37,122.28 119.79,122.86 119.79,122.86 119.67,122.99 119.67,123.47 120.25,124.05 120.87,124.05 120.99,124.18 123.17,124.18 123.24,124.11 123.24,122.69 123.67,122.25 125.68,122.25 125.89,122.04 125.89,119.81 125.38,119.31
PWR_VCCGT_SWB on BOTTOM: 111.15,119.26 110.39,120.02 110.39,123.74 110.94,124.3 113.96,124.3 114.02,124.23 114.02,122.7 114.31,122.4 115.34,122.4 115.63,122.12 115.63,119.66 115.23,119.26
PWR_VCCSA_BST on TOP: 131.91,135.49 131.71,135.69 131.71,136.15 131.78,136.22 132.7,136.22 132.93,136.45 133.56,136.45 133.69,136.32 133.69,135.66 133.51,135.49
PWR_VCCSA_DRVH on TOP: 131.27,128.94 131.18,129.03 131.18,130.15 131.35,130.32 132.96,130.32 132.97,130.31 133.58,130.31 133.62,130.26 133.62,129.57 133.49,129.44 133.48,129.44 133.12,129.08 132.71,129.08 132.57,128.94
PWR_VCCSA_FB1 on BOTTOM: 114.06,140.31 113.9,140.47 113.9,140.95 113.91,140.97 115.99,140.97 116.19,140.77 116.19,140.36 116.14,140.31
PWR_VCCSA_FB2 on TOP: 114.99,140.34 114.92,140.41 114.92,140.79 114.87,140.85 114.87,142.42 114.97,142.52 116.26,142.52 116.34,142.45 116.34,142.06 116.32,142.05 116.32,140.7 115.96,140.34 ; 2 cut-outs
PWR_VCCSA_SW on TOP: 131.05,131.56 130.77,131.84 130.77,132.35 131.19,132.77 133.05,132.77 133.61,132.21 133.61,131.7 133.48,131.56 ; 2 cut-outs
PWR_VCCSA_SW on BOTTOM: 133.17,119.3 132.88,119.59 132.88,122.8 132.99,122.91 135.18,122.91 135.45,123.18 135.45,124.57 135.62,124.74 138.71,124.74 138.76,124.69 138.76,119.45 138.61,119.3
PWR_VCORE_BOOT on BOTTOM: 105.32,127.02 105.3,127.04 105.3,127.74 105.3,127.74 105.3,129.65 105.47,129.82 106.49,129.82 106.61,129.7 106.61,128.68 106.02,128.09 105.82,128.09 105.52,127.79 105.52,127.06 105.49,127.02
PWR_VCORE_BOOTR on BOTTOM: 104.96,127.04 104.91,127.09 104.91,127.78 103.88,128.81 103.88,129.65 104.03,129.8 105.13,129.8 105.16,129.77 105.16,128.01 105.17,128.01 105.17,127.89 105.1,127.82 105.1,127.1 105.05,127.04 ; 1 cut-out
PWR_VCORE_FB on TOP: 118.45,137.42 118.32,137.54 118.32,137.92 118.45,138.05 119.91,138.05 120.26,138.4 120.26,138.93 120.48,139.15 121.14,139.15 121.3,138.98 121.3,138.73 120.61,138.04 120.61,137.52 120.5,137.42
PWR_VCORE_PWM_R on BOTTOM: 107.47,127.93 106.93,127.93 106.02,127.02 105.77,127.02 105.71,127.08 105.71,127.73 105.91,127.93 106.04,127.93 106.82,128.72 106.82,129.47 106.87,129.52 108.24,129.52 108.33,129.43 108.33,128.79 ; 2 cut-outs
PWR_VCORE_SW on BOTTOM: 101.83,119.36 100.8,120.39 100.8,123.57 101.62,124.4 104.63,124.4 104.69,124.33 104.69,122.8 104.99,122.5 106.02,122.5 106.3,122.22 106.3,119.75 105.91,119.36
PWR_VDDQ_HG on TOP: 39.53,23.78 39.45,23.85 39.45,24.92 39.22,25.15 39.22,25.71 39.4,25.88 39.78,25.88 39.94,25.73 39.94,25.22 39.66,24.94 39.66,23.85 39.58,23.78
PWR_VDDQ_HG on BOTTOM: 51.4,25.1 51.37,25.14 51.37,26.31 51.37,26.31 51.37,27 51.52,27.15 52.5,27.15 52.64,27.01 52.64,25.21 52.54,25.1
PWR_VDDQ_LG on TOP: 40.29,23.34 40.27,23.37 40.27,23.57 40.29,23.6 40.54,23.6 41.3,24.35 41.69,24.35 41.88,24.16 41.88,23.81 41.42,23.34
PWR_VDDQ_LG on BOTTOM: 44.31,21.94 44.14,22.11 44.14,23.05 44.24,23.15 45.37,23.15 45.41,23.12 45.41,21.95 45.4,21.94
PWR_VDDQ_PH on TOP: 39.89,23.73 39.86,23.75 39.86,24.94 40.14,25.22 40.14,27.13 40.21,27.2 41.16,27.2 41.23,27.12 41.23,25.28 40.1,24.14 40.1,23.76 40.06,23.73
PWR_VDDQ_PH on TOP: 46.16,25.15 46.11,25.2 46.11,26.09 46.17,26.14 48.55,26.14 48.75,25.94 48.75,25.42 48.48,25.15
PWR_VDDQ_PH on BOTTOM: 44.44,23.51 44.34,23.61 44.34,29.76 45.03,30.45 50.47,30.45 51.13,29.79 51.13,25.12 51.12,25.1 48.25,25.1 48.15,25 48.15,23.6 48.06,23.51
PWR_VDDQ_SNUB on TOP: 46.22,22.66 46.13,22.75 46.13,24.42 46.16,24.45 48.38,24.45 48.77,24.06 48.77,22.92 48.51,22.66 ; 2 cut-outs
PWR_VDDQ_VLDOIN on TOP: 38.67,23.73 38.65,23.75 38.65,24.73 38.35,25.04 37.69,25.04 37.19,25.53 37.19,26.29 36.81,26.67 35.8,26.67 35.67,26.8 35.67,27.69 35.8,27.82 37.31,27.82 37.57,27.55 38.44,27.55 38.58,27.42 38.58,26.16 38.43,26.01 38.43,25.27 38.88,24.82 38.88,23.75 38.87,23.73 ; 2 cut-outs
PWR_VDDQ_VTT on TOP: 37,22.94 36.67,23.27 33.4,23.27 33.25,23.42 33.25,24.76 33.39,24.9 38.27,24.9 38.48,24.69 38.48,23.74 38.47,23.73 38.27,23.73 38.23,23.77 38.23,24.22 38.08,24.37 37.22,24.37 37.03,24.18 37.03,23.2 37.08,23.15 38.07,23.15 38.07,23.15 38.07,22.97 38.05,22.94 ; 3 cut-outs
PWR_VGA_CORE_LGATE1 on TOP: 173.22,110.64 173.22,111.53 173.35,111.66 174.75,111.66 174.88,111.53 174.88,110.77 174.75,110.64
PWR_VGA_CORE_LGATE1 on BOTTOM: 168.72,110.54 168.59,110.66 168.59,111.43 168.72,111.55 170.11,111.55 170.24,111.43 170.24,110.66 170.11,110.54
PWR_VGA_CORE_LGATE2 on TOP: 168.7,103.61 168.57,103.74 168.57,104.5 168.7,104.62 170.1,104.62 170.22,104.5 170.22,103.61
PWR_VGA_CORE_LGATE2 on BOTTOM: 173.26,103.59 173.26,104.6 174.78,104.6 174.91,104.48 174.91,103.72 174.78,103.59
PWR_VGA_CORE_LGATE_NB on BOTTOM: 160.98,103.83 160.73,104.09 160.73,104.58 160.88,104.74 161.78,104.74 162.06,105.02 162.06,105.63 162.48,106.05 162.48,107.08 162.5,107.1 162.67,107.1 162.71,107.07 162.71,104.83 162.18,104.3 162.18,103.97 162.04,103.83 ; 1 cut-out
PWR_VGA_CORE_PHASE1 on TOP: 175.15,108.96 175.02,109.09 175.02,109.93 175.02,109.93 175.02,111.71 174.81,111.92 169.22,111.92 169.12,112.03 169.12,114.69 169.26,114.84 174.58,114.84 175,115.26 175,117.44 175.19,117.63 178.29,117.63 178.48,117.43 178.48,115.25 177.84,114.61 177.84,114 178.48,113.36 178.48,110.97 176.47,108.96 ; 1 cut-out
PWR_VGA_CORE_PHASE1 on BOTTOM: 175.18,110.6 173.87,111.91 168.81,111.91 168.59,112.12 168.59,114.7 168.74,114.85 174.73,114.85 174.92,115.04 174.92,115.77 174.89,115.8 174.89,117.34 175.18,117.63 178.29,117.63 178.48,117.44 178.48,115.25 177.9,114.66 177.08,114.66 177.03,114.62 177.03,113.61 177.08,113.56 178.29,113.56 178.48,113.37 178.48,110.89 178.19,110.6
PWR_VGA_CORE_PHASE2 on TOP: 174.7,98.02 174.49,98.23 174.49,100.06 174.29,100.26 169.17,100.26 169.09,100.33 169.09,103.15 169.12,103.17 174.48,103.17 175.12,103.81 175.12,104.94 174.78,105.27 174.78,106.03 174.85,106.1 176.8,106.1 178.14,104.76 178.67,104.76 178.87,104.56 178.87,102.16 177.9,101.19 177.9,100.27 178.48,99.69 178.48,98.4 178.1,98.02 ; 1 cut-out
PWR_VGA_CORE_PHASE2 on BOTTOM: 175.39,98.02 175.28,98.13 175.28,99.89 174.9,100.27 168.59,100.27 168.48,100.38 168.48,103.04 168.62,103.18 173.74,103.18 175.11,104.55 178.75,104.55 178.91,104.39 178.91,102.2 178.31,101.6 178.31,99.86 178.49,99.68 178.49,98.41 178.1,98.02
PWR_VGA_CORE_UGATE1 on TOP: 173.37,116.65 173.25,116.78 173.25,117.54 173.37,117.67 174.77,117.67 174.85,117.59 174.85,116.73 174.77,116.65
PWR_VGA_CORE_UGATE1 on BOTTOM: 168.58,116.53 168.46,116.65 168.46,117.42 168.58,117.54 170.11,117.54 170.23,117.42 170.23,116.65 170.11,116.53
PWR_VGA_CORE_UGATE2 on TOP: 168.68,97.52 168.55,97.65 168.55,98.45 168.72,98.62 170.14,98.62 170.22,98.54 170.22,97.56 170.18,97.52
PWR_VGA_CORE_UGATE2 on BOTTOM: 173.28,97.56 173.28,98.45 173.4,98.57 174.8,98.57 174.93,98.45 174.93,97.68 174.8,97.56
PWR_VGA_CORE_UGATE_LX_NB on BOTTOM: 163.36,104.03 162.88,104.51 162.88,107.04 162.96,107.12 163.46,107.12 163.49,107.09 163.49,104.92 163.87,104.55 163.87,104.07 163.82,104.03 ; 1 cut-out
PWR_VGA_SNUB1 on TOP: 173.97,107.72 173.86,107.83 173.86,108.33 174.07,108.54 175.75,108.54 175.81,108.48 175.81,107.81 175.72,107.72 ; 1 cut-out
PWR_VGA_SNUB2 on TOP: 174.11,106.61 173.9,106.83 173.9,107.33 173.97,107.4 175.77,107.4 175.82,107.34 175.82,106.68 175.75,106.61
REGOUT on TOP: 50.23,175.94 50.18,175.99 50.18,176.61 50.19,176.61 50.19,176.96 50.85,177.62 50.85,178.96 51.12,179.23 51.12,179.77 51.73,180.38 53.82,180.38 54.66,179.54 55.57,179.54 55.66,179.44 55.66,178.61 55.59,178.55 53.29,178.55 53.28,178.56 52.79,178.56 52.36,178.13 52.36,177.1 51.21,175.94 ; 2 cut-outs
RING2 on BOTTOM: 181.5,16.82 180.68,17.64 180.68,18.17 180.76,18.25 181.39,18.25 181.71,17.94 183.07,17.94 183.15,17.86 183.15,16.88 183.09,16.82
RING2 on BOTTOM: 174.48,19.61 174.43,19.66 174.43,19.8 174.46,19.84 175.04,19.84 175.94,20.73 176.89,20.73 177.02,20.6 177.02,20.13 176.86,19.96 176.54,19.96 176.51,19.99 175.78,19.99 175.4,19.61
RING2_R on BOTTOM: 183.76,16.68 183.68,16.75 183.68,17.75 183.75,17.82 187.59,17.82 187.99,18.21 190.38,18.21 190.41,18.18 190.41,16.87 190.24,16.87 190.23,16.88 188.25,16.88 188.05,16.68
RTC_PWR on TOP: 37.24,37.19 37.11,37.32 37.11,37.86 37.62,38.37 37.62,38.93 37.51,39.04 36.15,39.04 35.98,39.22 35.98,40.62 36.13,40.77 37.47,40.77 37.69,40.99 37.69,41.22 38.04,41.57 39.01,41.57 39.24,41.33 39.24,38.57 39.24,38.57 39.24,38.53 37.9,37.19 ; 2 cut-outs
SLEEVE on BOTTOM: 181.86,18.09 181.47,18.48 180.76,18.48 180.7,18.54 180.7,18.95 180.7,18.95 180.7,20.1 180.79,20.18 182.09,20.18 182.38,19.9 182.38,19.49 182.71,19.15 183.12,19.15 183.24,19.03 183.24,18.16 183.17,18.09 ; 1 cut-out
SLEEVE on BOTTOM: 175.62,19.04 175.45,19.22 174.45,19.22 174.43,19.23 174.43,19.43 174.44,19.44 175.35,19.44 175.7,19.8 176.25,19.8 176.34,19.7 176.34,19.32 176.06,19.04
SLEEVE_R on TOP: 187.99,18.21 187.81,18.4 187.81,19.93 188.12,20.25 188.14,20.25 188.91,21.02 190.15,21.02 190.41,20.77 190.41,19.75 188.87,18.21
SLEEVE_R on BOTTOM: 183.78,17.94 183.69,18.02 183.69,19.04 183.77,19.12 186.94,19.12 187.54,19.72 190.39,19.72 190.42,19.69 190.42,18.41 190.41,18.4 187.93,18.4 187.5,17.97 187.5,17.97 187.46,17.94
TP_VDD on BOTTOM: 145.46,14.08 145.35,14.19 145.35,15.31 145.53,15.49 146.49,15.49 146.76,15.76 146.76,19.62 147.04,19.9 147.57,19.9 149.13,21.46 149.13,21.47 149.93,22.27 149.93,22.85 150.07,22.99 151.32,22.99 151.57,22.73 151.57,20.39 151.37,20.19 150.72,20.19 150.72,20.19 150.11,20.19 148.71,18.79 148.71,18.08 148.08,17.45 148.08,14.14 148.03,14.08 ; 6 cut-outs
TP_VDD on BOTTOM: 140.38,17.26 140.29,17.35 140.29,17.84 141.46,19.02 141.46,21.62 141.59,21.74 142.67,21.74 142.73,21.68 142.73,20.63 143.59,19.77 143.84,19.77 144.52,19.1 144.52,17.59 144.19,17.26 ; 7 cut-outs
TP_VDD on L4: 143.08,18.81 146.84,18.81 147.39,18.26 147.39,16.47 147.26,16.34 143.7,16.34 142.92,17.12 142.92,18.65
TPAN_VDD on TOP: 113.73,175.11 113.58,175.26 113.58,179.64 113.66,179.72 118.44,179.72 118.8,179.35 118.8,177.42 118.62,177.24 115.63,177.24 114.38,176 114.38,175.66 114.39,175.66 114.39,175.23 114.27,175.11 ; 5 cut-outs
TPAN_VDD_F on TOP: 113.67,180.21 113.6,180.28 113.6,182.64 113.68,182.72 118.43,182.72 118.5,182.65 118.5,182.35 119.01,181.84 119.74,181.84 119.84,181.74 119.84,180.49 119.56,180.21 ; 3 cut-outs
USB20_VCCA on TOP: 183.86,24.81 183.58,25.1 183.58,29.34 183.85,29.62 185.02,29.62 187.81,26.84 187.81,25.23 187.38,24.81 ; 6 cut-outs
USB20_VCCA on BOTTOM: 186.56,23.4 186.3,23.66 186.3,24.33 186.25,24.38 184.99,24.38 184.07,25.3 182.61,25.3 182.35,25.55 182.35,27.03 182.67,27.35 187.14,27.35 188.23,26.25 188.23,26 189.03,25.2 190.41,25.2 190.41,23.4
USB30_VCCC on TOP: 16.29,38.56 15.99,38.85 15.99,40.79 16.37,41.17 25.24,41.17 25.32,41.09 25.32,38.98 24.9,38.56 ; 8 cut-outs
USB30_VCCC on BOTTOM: 13.99,34.15 13.58,34.57 13.58,35.34 13.58,35.35 13.58,36.82 14.17,37.41 14.17,39.45 15.9,41.17 18.25,41.17 18.57,40.85 18.57,34.53 18.2,34.15
USB30_VCCC on L3: 13.9,15.47 13.62,15.75 13.62,18.77 15.35,20.5 15.35,39.91 15.93,40.49 18.35,40.49 18.9,39.93 18.9,36.39 19.34,35.96 19.34,34.54 19.75,34.14 19.75,24.21 19.79,24.16 19.79,19.53 19.08,18.82 19.08,16.97 17.58,15.47
V_SM_VREF_CNTB on TOP: 98.89,17.05 98.59,17.35 98.59,19.02 98.73,19.17 99.27,19.17 99.31,19.12 99.31,17.19 99.17,17.05
VGA_CORE on TOP: 183.29,124.91 183.11,125.1 183.11,127.18 183.26,127.33 184.46,127.33 184.54,127.24 184.54,126.47 184.55,125.07 184.39,124.91 ; 6 cut-outs
VGA_CORE on TOP: 161.56,102.17 161.46,102.28 161.46,102.81 161.53,102.87 162.75,102.87 162.9,102.72 162.9,102.36 162.71,102.17
VGA_CORE on TOP: 175.8,135.81 175.44,136.17 175.44,137.56 176.05,138.17 176.98,138.17 177.11,138.04 177.11,137.57 177.48,137.19 177.48,136.31 176.99,135.81 ; 5 cut-outs
VGA_CORE on TOP: 180.68,98.93 180.42,99.19 180.42,100.33 179.84,100.92 179.84,121.41 178.44,122.81 178.44,124.74 178.7,125 180.37,125 182.67,122.7 186.05,122.7 187.23,121.52 187.23,100.79 185.37,98.93 ; 2 cut-outs
VGA_CORE on TOP: outline of 88 points within 166.72,131.25 175.66,141.35 ; 18 cut-outs
VGA_CORE on TOP: 166.98,120.51 166.78,120.71 164.09,120.71 163.82,120.97 163.82,121.03 162.57,122.29 162.57,124.69 163.63,125.76 163.63,128.07 163.85,128.28 163.85,130.49 165.08,131.73 166.68,131.73 167.34,131.07 167.34,129.39 167.33,129.38 167.33,128.61 166.56,127.84 166.56,125.97 166.73,125.79 168.01,125.79 168.09,125.71 168.09,120.62 167.98,120.51 ; 8 cut-outs
VGA_CORE on BOTTOM: outline of 119 points within 167.12,99.03 187.41,141.34 ; 8 cut-outs
VGA_CORE on BOTTOM: 163.17,119.94 163.04,120.07 163.04,123.74 162.93,123.74 162.69,123.98 162.69,124.59 164.45,126.34 164.45,126.52 164.57,126.65 166.12,126.65 166.63,126.14 166.63,124.46 167.05,124.04 167.73,124.04 167.96,123.81 167.96,120.12 167.79,119.94 167.21,119.94 166.99,120.17 166.99,120.3 166.81,120.47 165.25,120.47 164.73,119.95 164.69,119.95 164.68,119.94 ; 6 cut-outs
VGA_CORE on L2: 187.85,100.97 186.08,99.19 179.52,99.19 179.25,99.46 179.25,117.99 178.4,118.83 172.78,118.83 172.25,119.36 165.94,119.36 164.87,120.43 162,120.43 161.79,120.63 161.79,126.06 161.91,126.18 161.89,126.2 163.84,128.15 163.84,131.6 163.14,132.3 163.14,134.57 161.78,135.93 161.78,139.59 163.16,140.97 177.05,140.97 185.87,132.15 185.87,132.08 187.85,130.1
VGA_CORE on L3: 186.07,125.99 186.07,127.48 185.57,127.99 185.57,131.52 183.64,133.44 175.92,141.16 168.21,141.16 167.87,140.82 167.87,136.41 168.19,136.09 168.19,135.09 168.43,134.84 170.5,134.84 171.35,133.99 173.35,133.99 174.16,134.8 175.33,134.8 176.03,134.1 176.03,131.25 177.93,129.34 177.93,123.4 179.87,121.46 179.87,99.86 180.28,99.44 187.59,99.44 188.36,100.22 188.36,123.7
VGA_CORE on L4: 170.37,136.04 170.83,135.57 177.56,135.57 177.73,135.74 177.73,136.63 175.97,138.38 172.04,138.38 171.2,137.54 170.82,137.54 170.37,137.09
VGA_CORE on L4: 163.25,122 162.78,122.47 162.78,123.26 162.77,123.27 162.77,125.71 163.74,126.67 166.07,126.67 167.22,125.53 167.42,125.53 167.42,126.47 166.07,127.81 166.07,127.99 166.02,128.04 166.02,132.72 167.09,133.78 167.12,133.78 167.12,135.5 167.28,135.66 170.02,135.66 171.03,134.65 173.75,134.65 175.27,133.13 183.24,133.13 183.4,132.97 183.4,131.09 182.81,130.51 174.24,130.51 173.46,131.28 171.21,131.28 170.38,130.45 170.38,129.86 170.67,129.57 170.67,127.92 169.35,126.6 169.35,126.27 166.33,123.24 166.07,123.24 164.83,122
VGA_CORE on L4: 185.08,122.46 185.17,122.46 185.58,122.04 186.71,122.04 188.32,120.44 188.32,100.25 187.49,99.42 181.41,99.42 180.12,100.72 180.12,112.47 180.42,112.78 180.42,116.33 180.25,116.51 180.25,118.57 179.86,118.95 179.86,121.26 179.08,122.05 179.08,124.03 181.03,125.99 183.93,125.99 184.44,125.48 184.44,123.09

Small or netless copper shapes (teardrops, artwork), in the pictures only: 2 on TOP, 5 on BOTTOM

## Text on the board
Ref Des/Silkscreen Bottom: X1801:24MHZ | X2201:24MHZ | X1802:32.768KHZ | X2401:32.768KHZ | X7901:27MHZ | MADE IN TAIWAN | WX2RR | 17841-1 | Vegas/Turis MLK KBL-R
Ref Des/Silkscreen Top: F5503:1.1A/24V | F5502:1.1A/24V | X3101:25MHZ | F5701:1.1A/6V | KB
